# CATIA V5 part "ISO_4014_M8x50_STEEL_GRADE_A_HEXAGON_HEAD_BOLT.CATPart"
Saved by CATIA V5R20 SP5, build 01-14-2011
Part number: ISO 4014 BOLT M8x50 STEEL GRADE A HEXAGON HEAD
Publications: "Mating Face", "Axis"
Bounding box of the stored display mesh (mm): x -50 to 5.45, y -6.5 to 6.5, z -7.506 to 7.506
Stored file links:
  E:\scc\ISO_4014_M8x50_STEEL_GRADE_A_HEXAGON_HEAD_BOLT.CATPart
  C:\Program Files\Dassault Systemes\B20\intel_a\startup\components\MechanicalStandardParts\EN_Standards\Design_Tables\EN_ISO_4014_GRADES_A_B_HEXAGON_HEAD_BOLT.txt
  C:\Program Files\Dassault Systemes\B20\intel_a\startup\components\MechanicalStandardParts\ISO_Standards\Design_Tables\ISO_4014_GRADES_A_B_HEXAGON_HEAD_BOLT.txt
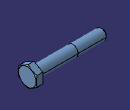
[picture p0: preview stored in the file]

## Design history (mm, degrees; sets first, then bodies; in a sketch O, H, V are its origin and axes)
Parameters
  d_dia = 8 mm
  l_length = 50 mm
  s_nom_across_flats = 13 mm
  k_max_head_depth = 5.45 mm
  dw_min = 11.63 mm
  r_min = 0.4 mm
  c_max = 0.6 mm
  p_pitch = 1.25 mm
  threading = 22 mm
Body1 "PartBody" (main body)
  Sketch1 on yz-plane, origin (0, 0, 0), H (0, 1, 0), V (0, 0, 1)
    circle A1 centre (0, 0) radius 5.815
    radius A1 = 5.815 {= dw_min /2}
  Pad1: profile Sketch1, direction (1, 0, 0), length 0.6 {= c_max}
  Sketch2 on face of Pad1, origin (0.6, 0, 0), H (0, 1, 0), V (0, 0, 1)
    point P1 (6.5, -3.7528)
    point P2 (6.5, 3.7528)
    point P3 (0, 7.5056)
    point P4 (-6.5, 3.7528)
    point P5 (-6.5, -3.7528)
    point P6 (0, -7.5056)
    point P7 (6.5, 0)
    line L1 (6.5, -3.7528) -> (6.5, 3.7528)
    line L2 (6.5, 3.7528) -> (0, 7.5056)
    line L3 (0, 7.5056) -> (-6.5, 3.7528)
    line L4 (-6.5, 3.7528) -> (-6.5, -3.7528)
    line L5 (-6.5, -3.7528) -> (0, -7.5056)
    line L6 (0, -7.5056) -> (6.5, -3.7528)
    construction line L7 (0, 0) -> (6.5, 0)
    construction circle A1 centre (0, 0) radius 7.5056
    construction arc A2 centre (-6.5, -3.7528) radius 7.5056 from (-6.5, 3.7528) to (0, -7.5056) cw
    construction arc A3 centre (6.5, 3.7528) radius 7.5056 from (0, 7.5056) to (6.5, -3.7528) ccw
    point P8 (-6.5, -3.7528)
    point P9 (6.5, 3.7528)
    distance L1 L4 = 13 {= s_nom_across_flats}
    horizontal: L7 H
    coincidence: A1 P1, A1 P2, A1 P3, A1 P4, A1 P5, A1 P6, A2 P4, A2 P6, A2 O, P8 P5, A3 P3, A3 P1, A3 O, P9 P2
    midpoint: P7 L1
  Pad2: profile Sketch2, direction (1, 0, 0), length 4.85 {= k_max_head_depth -c_max}
  Sketch3 on zx-plane, origin (0, 0, 0), H (-1, 0, 0), V (0, 0, 1)
    point P1 (-5.45, 6.4709)
    axis line L1 (-94.6904, 0) -> (76.7146, 0)
    reference intersected line E1 through (1000000, 0) direction (-1, 0) from xy-plane
    line L2 (-4.8526, 7.5056) -> (-5.45, 6.4709)
    line L3 (-4.8526, 7.5056) -> (-5.45, 7.5056)
    line L4 (-5.45, 7.5056) -> (-5.45, 6.4709)
    reference projected line E2 (-0.8, 7.5056) -> (-18.28, 7.5056) from edge [face of Pad2 | face of Pad2]
    distance P1 H = 6.4709 {= s_nom_across_flats /2.009}
    distance P1 V = 5.45 {= k_max_head_depth}
    angle L4 L2 = 30
    horizontal: L1 H, L3 H
    coincidence: L1 E1, L3 E2
    vertical: L4 V
  Groove1: profile Sketch3, axis Sketch3.L1, angle 360
  Sketch4 on face of Pad1, origin (0, 0, 0), H (0, -1, 0), V (0, 0, 1)
    circle A1 centre (0, 0) radius 4
    radius A1 = 4 {= d_dia /2}
  Pad3: profile Sketch4, direction (-1, 0, 0), length 28 {= l_length -threading}
  Sketch5 on face of Pad3, origin (-28, 0, 0), H (0, -1, 0), V (0, 0, 1)
    circle A1 centre (0, 0) radius 3.9024
    radius A1 = 3.9024 {= d_dia /2.05}
  Pad4: profile Sketch5, direction (-1, 0, 0), length 22 {= threading}
  Chamfer1: length 1.25 {= p_pitch}, angle 45, on face of Pad4
  Fillet1: radius 0.4 {= r_min}, on edge [face of Pad3 | face of Pad1]
  Thread1: diameter 7.8049 {= d_dia /1.025}, depth 22 {= threading}, pitch 1, on face of Pad4, from face of Pad4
